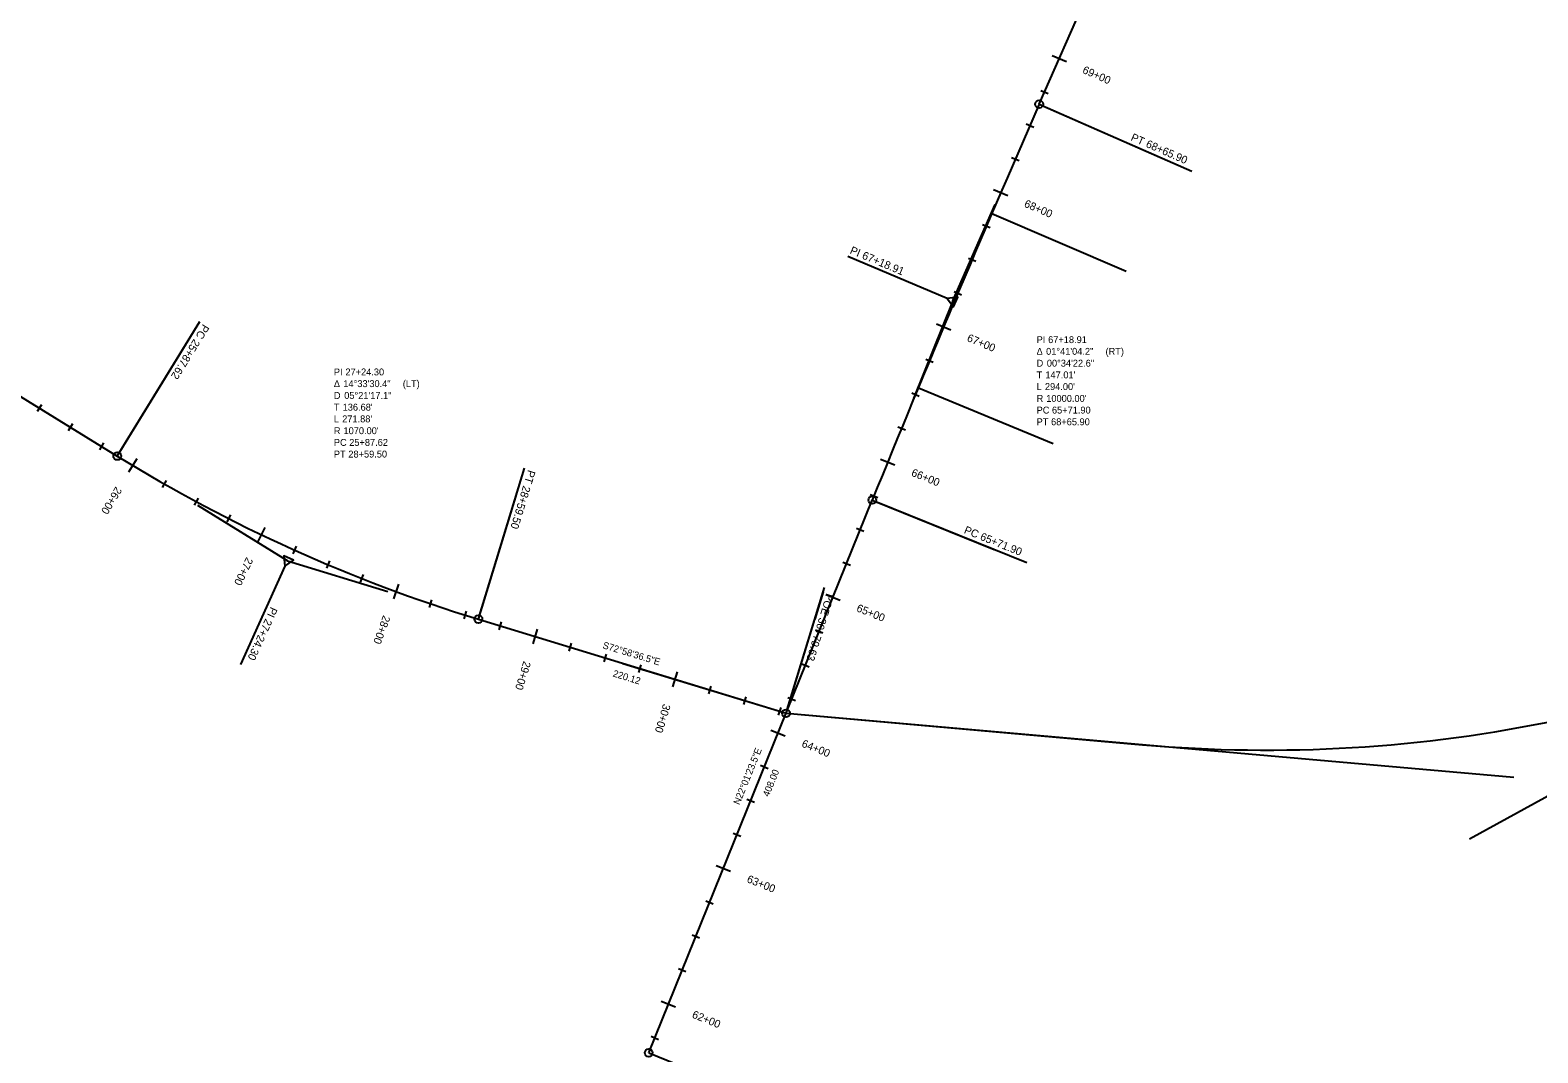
# Model space of a CAD drawing. Extents: x 2307903 to 2339201, y 758183 to 762824.
# Drawn here: x 2320206 to 2321238, y 759343 to 760043 of the extents above; entities that cross this region are included whole.
import ezdxf

# ---------------------------------------------------------------- set-up
doc = ezdxf.new("R2010")
doc.units = 0
for name, color, linetype in [('Default', 7, 'Continuous'), ('E_Terrain_Contour_Imported', 7, 'Continuous'), ('E_Terrain_Contour_Major', 7, 'Continuous'), ('E_Terrain_Flow_Arrows', 7, 'Continuous'), ('E_Terrain_Hole', 7, 'Continuous'), ('E_Terrain_Island', 7, 'Continuous'), ('E_Terrain_Points_High', 7, 'Continuous'), ('E_Terrain_Points_Low', 7, 'Continuous'), ('E_Terrain_SpotElevation', 7, 'Continuous'), ('Geom_Baseline', 7, 'Continuous'), ('Geom_Driveway_Centerline', 7, 'Continuous')]:
    doc.layers.add(name, color=color, linetype=linetype)

msp = doc.modelspace()

# ---------------------------------------------------------------- linework, layer by layer
at = {"layer": 'Default'}
for p, q in [((2320896.6, 759992.2), (2321353.4, 761032.3)), ((2320896.6, 759992.2), (2321353.4, 761032.3)), ((2320896.6, 759992.2), (2321353.4, 761032.3)), ((2320896.6, 759992.2), (2321353.4, 761032.3)), ((2321191, 759489.6), (2322195.4, 760040.5)), ((2320905.4, 760025.6), (2320915.2, 760021.3)), ((2319840.1, 760013), (2320265.8, 759751.4)), ((2320897.8, 760001.6), (2320902.8, 759999.4)), ((2320887.7, 759978.7), (2320892.8, 759976.5)), ((2320877.7, 759955.8), (2320882.8, 759953.6)), ((2320865.4, 759933.9), (2320875.2, 759929.7)), ((2320857.9, 759909.9), (2320863, 759907.7)), ((2320848.1, 759886.9), (2320853.2, 759884.7)), ((2320838.3, 759863.9), (2320843.4, 759861.7)), ((2320826.3, 759841.8), (2320836.1, 759837.7)), ((2320819, 759817.7), (2320824.1, 759815.6)), ((2320809.4, 759794.6), (2320814.5, 759792.5)), ((2320213.9, 759786.5), (2320211, 759781.8)), ((2320235.1, 759773.4), (2320232.3, 759768.7)), ((2320799.9, 759771.5), (2320805, 759769.4)), ((2320256.4, 759760.4), (2320253.6, 759755.6)), ((2320279.1, 759749.6), (2320273.6, 759740.4)), ((2320788, 759749.3), (2320797.9, 759745.3)), ((2320299.3, 759734.8), (2320296.6, 759730)), ((2320321.1, 759722.7), (2320318.5, 759717.9)), ((2320629.4, 759343.1), (2320782.4, 759721.3)), ((2320629.4, 759343.1), (2320782.4, 759721.3)), ((2320629.4, 759343.1), (2320782.4, 759721.3)), ((2320629.4, 759343.1), (2320782.4, 759721.3)), ((2320629.4, 759343.1), (2320782.4, 759721.3)), ((2320781, 759725.2), (2320786.1, 759723.1)), ((2320343.2, 759711.2), (2320340.7, 759706.3)), ((2320366.7, 759702.5), (2320362.1, 759692.9)), ((2320771.6, 759702), (2320776.7, 759700)), ((2320388.2, 759689.7), (2320385.9, 759684.6)), ((2320411.1, 759679.7), (2320408.9, 759674.6)), ((2320434.1, 759670.3), (2320432.1, 759665.1)), ((2320762.2, 759678.9), (2320767.4, 759676.8)), ((2320458.3, 759663.8), (2320454.7, 759653.8)), ((2320480.9, 759653), (2320479.2, 759647.8)), ((2320750.5, 759656.6), (2320760.3, 759652.7)), ((2320504.6, 759645.3), (2320503, 759640)), ((2320512.9, 759639.8), (2320723.4, 759575.4)), ((2320528.5, 759637.9), (2320526.9, 759632.6)), ((2320553.2, 759633), (2320550.1, 759622.9)), ((2320743.5, 759632.5), (2320748.6, 759630.4)), ((2320576.3, 759623.3), (2320574.7, 759618)), ((2320600.2, 759615.9), (2320598.6, 759610.7)), ((2320611.8, 759609.5), (2320723.4, 759575.4)), ((2320624.1, 759608.6), (2320622.5, 759603.3)), ((2320734.1, 759609.3), (2320739.2, 759607.3)), ((2320648.8, 759603.8), (2320645.7, 759593.6)), ((2320671.9, 759594), (2320670.3, 759588.7)), ((2320695.8, 759586.7), (2320694.2, 759581.4)), ((2320724.7, 759586.1), (2320729.9, 759584.1)), ((2320719.7, 759579.3), (2320718.1, 759574.1)), ((2320713, 759563.9), (2320722.8, 759560)), ((2320706, 759539.8), (2320711.1, 759537.7)), ((2320696.6, 759516.6), (2320701.7, 759514.6)), ((2320687.2, 759493.4), (2320692.4, 759491.4)), ((2320675.5, 759471.2), (2320685.3, 759467.3)), ((2320668.5, 759447.1), (2320673.6, 759445)), ((2320659.1, 759423.9), (2320664.2, 759421.8)), ((2320649.7, 759400.7), (2320654.9, 759398.7)), ((2320638, 759378.5), (2320647.8, 759374.6)), ((2320631, 759354.4), (2320636.1, 759352.3))]:
    msp.add_line(p, q, dxfattribs=at)
for centre, radius, start, end in [((2330052.7, 755971.5), 10000, 156.2923, 157.9768), ((2330052.7, 755971.5), 10000, 156.2923, 157.9768), ((2330052.7, 755971.5), 10000, 156.2923, 157.9768), ((2330052.7, 755971.5), 10000, 156.2923, 157.9768), ((2330052.7, 755971.5), 10000, 156.2923, 157.9768), ((2320826.1, 760662.9), 1070, 238.4184, 252.9768)]:
    msp.add_arc(centre, radius, start, end, dxfattribs=at)
at = {"layer": 'E_Terrain_Contour_Imported'}
for p, q in [((2320897.8, 760001.6), (2320902.8, 759999.4)), ((2320887.7, 759978.7), (2320892.8, 759976.5)), ((2320877.7, 759955.8), (2320882.8, 759953.6)), ((2320857.9, 759909.9), (2320863, 759907.7)), ((2320848.1, 759886.9), (2320853.2, 759884.7)), ((2320838.3, 759863.9), (2320843.4, 759861.7)), ((2320819, 759817.7), (2320824.1, 759815.6)), ((2320809.4, 759794.6), (2320814.5, 759792.5)), ((2320213.9, 759786.5), (2320211, 759781.8)), ((2320235.1, 759773.4), (2320232.3, 759768.7)), ((2320799.9, 759771.5), (2320805, 759769.4)), ((2320256.4, 759760.4), (2320253.6, 759755.6)), ((2320299.3, 759734.8), (2320296.6, 759730)), ((2320321.1, 759722.7), (2320318.5, 759717.9)), ((2320781, 759725.2), (2320786.1, 759723.1)), ((2320343.2, 759711.2), (2320340.7, 759706.3)), ((2320771.6, 759702), (2320776.7, 759700)), ((2320388.2, 759689.7), (2320385.9, 759684.6)), ((2320411.1, 759679.7), (2320408.9, 759674.6)), ((2320434.1, 759670.3), (2320432.1, 759665.1)), ((2320762.2, 759678.9), (2320767.4, 759676.8)), ((2320480.9, 759653), (2320479.2, 759647.8)), ((2320504.6, 759645.3), (2320503, 759640)), ((2320528.5, 759637.9), (2320526.9, 759632.6)), ((2320743.5, 759632.5), (2320748.6, 759630.4)), ((2320576.3, 759623.3), (2320574.7, 759618)), ((2320600.2, 759615.9), (2320598.6, 759610.7)), ((2320624.1, 759608.6), (2320622.5, 759603.3)), ((2320734.1, 759609.3), (2320739.2, 759607.3)), ((2320671.9, 759594), (2320670.3, 759588.7)), ((2320695.8, 759586.7), (2320694.2, 759581.4)), ((2320724.7, 759586.1), (2320729.9, 759584.1)), ((2320719.7, 759579.3), (2320718.1, 759574.1)), ((2320706, 759539.8), (2320711.1, 759537.7)), ((2320696.6, 759516.6), (2320701.7, 759514.6)), ((2320687.2, 759493.4), (2320692.4, 759491.4)), ((2320668.5, 759447.1), (2320673.6, 759445)), ((2320659.1, 759423.9), (2320664.2, 759421.8)), ((2320649.7, 759400.7), (2320654.9, 759398.7)), ((2320631, 759354.4), (2320636.1, 759352.3))]:
    msp.add_line(p, q, dxfattribs=at)
at = {"layer": 'E_Terrain_Hole'}
for p, q in [((2319840.1, 760013), (2320265.8, 759751.4)), ((2320512.9, 759639.8), (2320723.4, 759575.4)), ((2320723.4, 759575.4), (2321221.4, 759531.6)), ((2320723.4, 759575.4), (2320967.3, 759553.9)), ((2320723.4, 759575.4), (2320967.3, 759553.9))]:
    msp.add_line(p, q, dxfattribs=at)
for centre, radius, start, end in [((2320826.1, 760662.9), 1070, 238.4184, 252.9768), ((2320826.1, 760662.9), 1070, 238.4184, 252.9768), ((2321052.4, 760522.2), 972, 264.9768, 298.7415), ((2321052.4, 760522.2), 972, 264.9768, 298.7415)]:
    msp.add_arc(centre, radius, start, end, dxfattribs=at)
at = {"layer": 'E_Terrain_Island'}
for p, q in [((2320905.4, 760025.6), (2320915.2, 760021.3)), ((2320865.4, 759933.9), (2320875.2, 759929.7)), ((2320826.3, 759841.8), (2320836.1, 759837.7)), ((2320279.1, 759749.6), (2320273.6, 759740.4)), ((2320788, 759749.3), (2320797.9, 759745.3)), ((2320366.7, 759702.5), (2320362.1, 759692.9)), ((2320458.3, 759663.8), (2320454.7, 759653.8)), ((2320750.5, 759656.6), (2320760.3, 759652.7)), ((2320553.2, 759633), (2320550.1, 759622.9)), ((2320648.8, 759603.8), (2320645.7, 759593.6)), ((2320713, 759563.9), (2320722.8, 759560)), ((2320675.5, 759471.2), (2320685.3, 759467.3)), ((2320638, 759378.5), (2320647.8, 759374.6))]:
    msp.add_line(p, q, dxfattribs=at)
at = {"layer": 'E_Terrain_Points_High'}
for p, q in [((2320899.1, 759991.1), (2321001, 759946.3)), ((2320837.5, 759857.6), (2320866.5, 759923.5)), ((2320833.6, 759859.2), (2320765.6, 759887.9)), ((2320837.5, 759857.6), (2320810.5, 759790.8)), ((2320837.5, 759857.6), (2320837.5, 759857.6)), ((2320267.2, 759753.7), (2320322.3, 759843.4)), ((2320513.7, 759642.4), (2320544.5, 759743.1)), ((2320784.9, 759720.3), (2320888.1, 759678.5)), ((2320382.2, 759679.8), (2320320.9, 759717.5)), ((2320382.2, 759679.8), (2320382.2, 759679.8)), ((2320382.2, 759679.8), (2320451, 759658.7)), ((2320380.5, 759676), (2320350.1, 759608.7))]:
    msp.add_line(p, q, dxfattribs=at)
for points in [[(2320833.7, 759859.2), (2320838, 759853.5), (2320840.8, 759860.1)], [(2320833.7, 759859.2), (2320838, 759853.5), (2320840.8, 759860.1)], [(2320380.5, 759676), (2320386.3, 759680.2), (2320379.8, 759683.2)], [(2320380.5, 759676), (2320386.3, 759680.2), (2320379.8, 759683.2)]]:
    msp.add_lwpolyline(points, close=True, dxfattribs=at)
at = {"layer": 'E_Terrain_SpotElevation'}
for p, q in [((2320896.6, 759992.2), (2320979, 759956)), ((2320896.6, 759992.2), (2320896.6, 759992.2)), ((2321001, 759946.3), (2321001, 759946.3)), ((2320765.6, 759887.9), (2320765.6, 759887.9)), ((2320837.5, 759857.6), (2320837.5, 759857.6)), ((2320322.3, 759843.4), (2320322.3, 759843.4)), ((2320265.8, 759751.4), (2320312.9, 759828.1)), ((2320265.8, 759751.4), (2320265.8, 759751.4)), ((2320544.5, 759743.1), (2320544.5, 759743.1)), ((2320512.9, 759639.8), (2320539.2, 759725.9)), ((2320782.4, 759721.3), (2320865.8, 759687.5)), ((2320782.4, 759721.3), (2320782.4, 759721.3)), ((2320382.2, 759679.8), (2320382.2, 759679.8)), ((2320888.1, 759678.5), (2320888.1, 759678.5)), ((2320723.4, 759575.4), (2320749.7, 759661.4)), ((2320724.1, 759577.9), (2320748.8, 759658.5)), ((2320748.8, 759658.5), (2320743.1, 759639.7)), ((2320512.9, 759639.8), (2320512.9, 759639.8)), ((2320350.1, 759608.7), (2320350.1, 759608.7)), ((2320723.4, 759575.4), (2320723.4, 759575.4)), ((2320629.4, 759343.1), (2320712.8, 759309.3)), ((2320629.4, 759343.1), (2320629.4, 759343.1))]:
    msp.add_line(p, q, dxfattribs=at)
for centre in [(2320896.6, 759992.2), (2320896.6, 759992.2), (2320265.8, 759751.4), (2320265.8, 759751.4), (2320782.4, 759721.3), (2320782.4, 759721.3), (2320512.9, 759639.8), (2320512.9, 759639.8), (2320723.4, 759575.4), (2320723.4, 759575.4), (2320629.4, 759343.1), (2320629.4, 759343.1)]:
    msp.add_circle(centre, 2.67, dxfattribs=at)
at = {"layer": 'Geom_Baseline'}
for p, q in [((2320896.6, 759992.2), (2321353.4, 761032.3)), ((2320629.4, 759343.1), (2320782.4, 759721.3))]:
    msp.add_line(p, q, dxfattribs=at)
msp.add_arc((2330052.7, 755971.5), 10000, 156.2923, 157.9768, dxfattribs=at)
at = {"layer": 'Geom_Driveway_Centerline'}
for p, q in [((2320864.1, 759917.4), (2320956, 759877.9)), ((2320813.9, 759798.2), (2320906.2, 759759.9))]:
    msp.add_line(p, q, dxfattribs=at)

# ---------------------------------------------------------------- texts
at = {"layer": 'E_Terrain_Contour_Major'}
for s, rotation, p in [('69+00', 336.2923, (2320925.7, 760013.7)), ('68+00', 336.6699, (2320885.8, 759922.2)), ('67+00', 337.2428, (2320846.7, 759830.3)), ('66+00', 337.8158, (2320808.6, 759738.1)), ('26+00', 239.081, (2320264.8, 759730.9)), ('27+00', 244.4358, (2320354.2, 759682.6)), ('65+00', 337.9768, (2320771.1, 759645.4)), ('28+00', 249.7905, (2320447.8, 759642.8)), ('29+00', 252.9768, (2320543.8, 759611.5)), ('30+00', 252.9768, (2320639.4, 759582.2)), ('64+00', 337.9768, (2320733.6, 759552.7)), ('63+00', 337.9768, (2320696.1, 759460)), ('62+00', 337.9768, (2320658.6, 759367.3))]:
    msp.add_text(s, height=5.34, rotation=rotation, dxfattribs=at).set_placement(p)
at = {"layer": 'E_Terrain_Flow_Arrows'}
for s, height, rotation, p in [('S72°58\'36.5"E', 4.724, 342.9768, (2320597.5, 759620)), ('220.12', 4.72, 342.9768, (2320604.5, 759600.7)), ('N22°01\'23.5"E', 4.724, 67.9768, (2320691.5, 759512.4)), ('408.00', 4.72, 67.9768, (2320711.6, 759517.9))]:
    msp.add_text(s, height=height, rotation=rotation, dxfattribs=at).set_placement(p)
at = {"layer": 'E_Terrain_Points_Low'}
for s, height, p in [('Δ ', 4.72, (2320894.8, 759820.7)), ('PI ', 4.72, (2320894.8, 759828.7)), ('01°41\'04.2"', 4.724, (2320901.3, 759820.7)), ('67+18.91', 4.72, (2320902.7, 759828.7)), (' (RT)', 4.72, (2320940.2, 759820.7)), ('D ', 4.72, (2320894.8, 759812.6)), ('00°34\'22.6"', 4.724, (2320901.8, 759812.6)), ('Δ ', 4.72, (2320414, 759798.6)), ('PI ', 4.72, (2320414, 759806.6)), ('14°33\'30.4"', 4.724, (2320420.5, 759798.6)), ('27+24.30', 4.72, (2320421.9, 759806.6)), (' (LT)', 4.72, (2320459.4, 759798.6)), ('T ', 4.72, (2320894.8, 759804.6)), ("147.01'", 4.72, (2320900.8, 759804.6)), ('D ', 4.72, (2320414, 759790.5)), ('05°21\'17.1"', 4.724, (2320421.1, 759790.5)), ('L ', 4.72, (2320894.8, 759796.6)), ('R ', 4.72, (2320894.8, 759788.5)), ("294.00'", 4.72, (2320900.5, 759796.6)), ("10000.00'", 4.72, (2320901.4, 759788.5)), ('T ', 4.72, (2320414, 759782.5)), ("136.68'", 4.72, (2320420, 759782.5)), ('PC ', 4.72, (2320894.8, 759780.5)), ('65+71.90', 4.72, (2320905.3, 759780.5)), ('L ', 4.72, (2320414, 759774.5)), ("271.88'", 4.72, (2320419.7, 759774.5)), ('PT ', 4.72, (2320894.8, 759772.5)), ('68+65.90', 4.72, (2320904.7, 759772.5)), ('R ', 4.72, (2320414, 759766.4)), ('PC ', 4.72, (2320414, 759758.4)), ("1070.00'", 4.72, (2320420.6, 759766.4)), ('25+87.62', 4.72, (2320424.5, 759758.4)), ('PT ', 4.72, (2320414, 759750.4)), ('28+59.50', 4.72, (2320423.9, 759750.4))]:
    msp.add_text(s, height=height, dxfattribs=at).set_placement(p)
at = {"layer": 'E_Terrain_SpotElevation'}
for s, height, rotation, p in [('PT', 5.34, 336.2923, (2320958.8, 759967.6)), ('68+65.90', 5.34, 336.2923, (2320969.1, 759963.1)), ('PI ', 5.4, 337.1345, (2320766.6, 759890.2)), ('67+18.91', 5.4, 337.1345, (2320774.9, 759886.7)), ('PC', 5.4, 238.4184, (2320324.5, 759842.1)), ('25+87.62', 5.4, 238.4184, (2320318.2, 759831.9)), ('PT', 5.4, 252.9768, (2320546.9, 759742.3)), ('28+59.50', 5.4, 252.9768, (2320543.6, 759731.5)), ('PC', 5.34, 337.9768, (2320844.7, 759698.8)), ('65+71.90', 5.34, 337.9768, (2320855.7, 759694.3)), ('PI ', 5.34, 245.6976, (2320370.8, 759648.6)), ('POE ', 5.4, 252.9768, (2320751.2, 759657.8)), ('27+24.30', 5.34, 245.6976, (2320367.2, 759640.5)), ('30+79.63', 5.4, 252.9768, (2320746.1, 759641.2))]:
    msp.add_text(s, height=height, rotation=rotation, dxfattribs=at).set_placement(p)

doc.saveas('drawing.dxf')
